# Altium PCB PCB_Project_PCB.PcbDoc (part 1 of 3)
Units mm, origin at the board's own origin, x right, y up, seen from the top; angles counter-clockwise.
Board outline 185 x 95 mm, 2 copper layers (Top Layer, Bottom Layer), stack 1.575 mm thick; 173 components, 93 nets, 424 pads, 126 vias.
Unrouted connection lines stored in the file: 1.
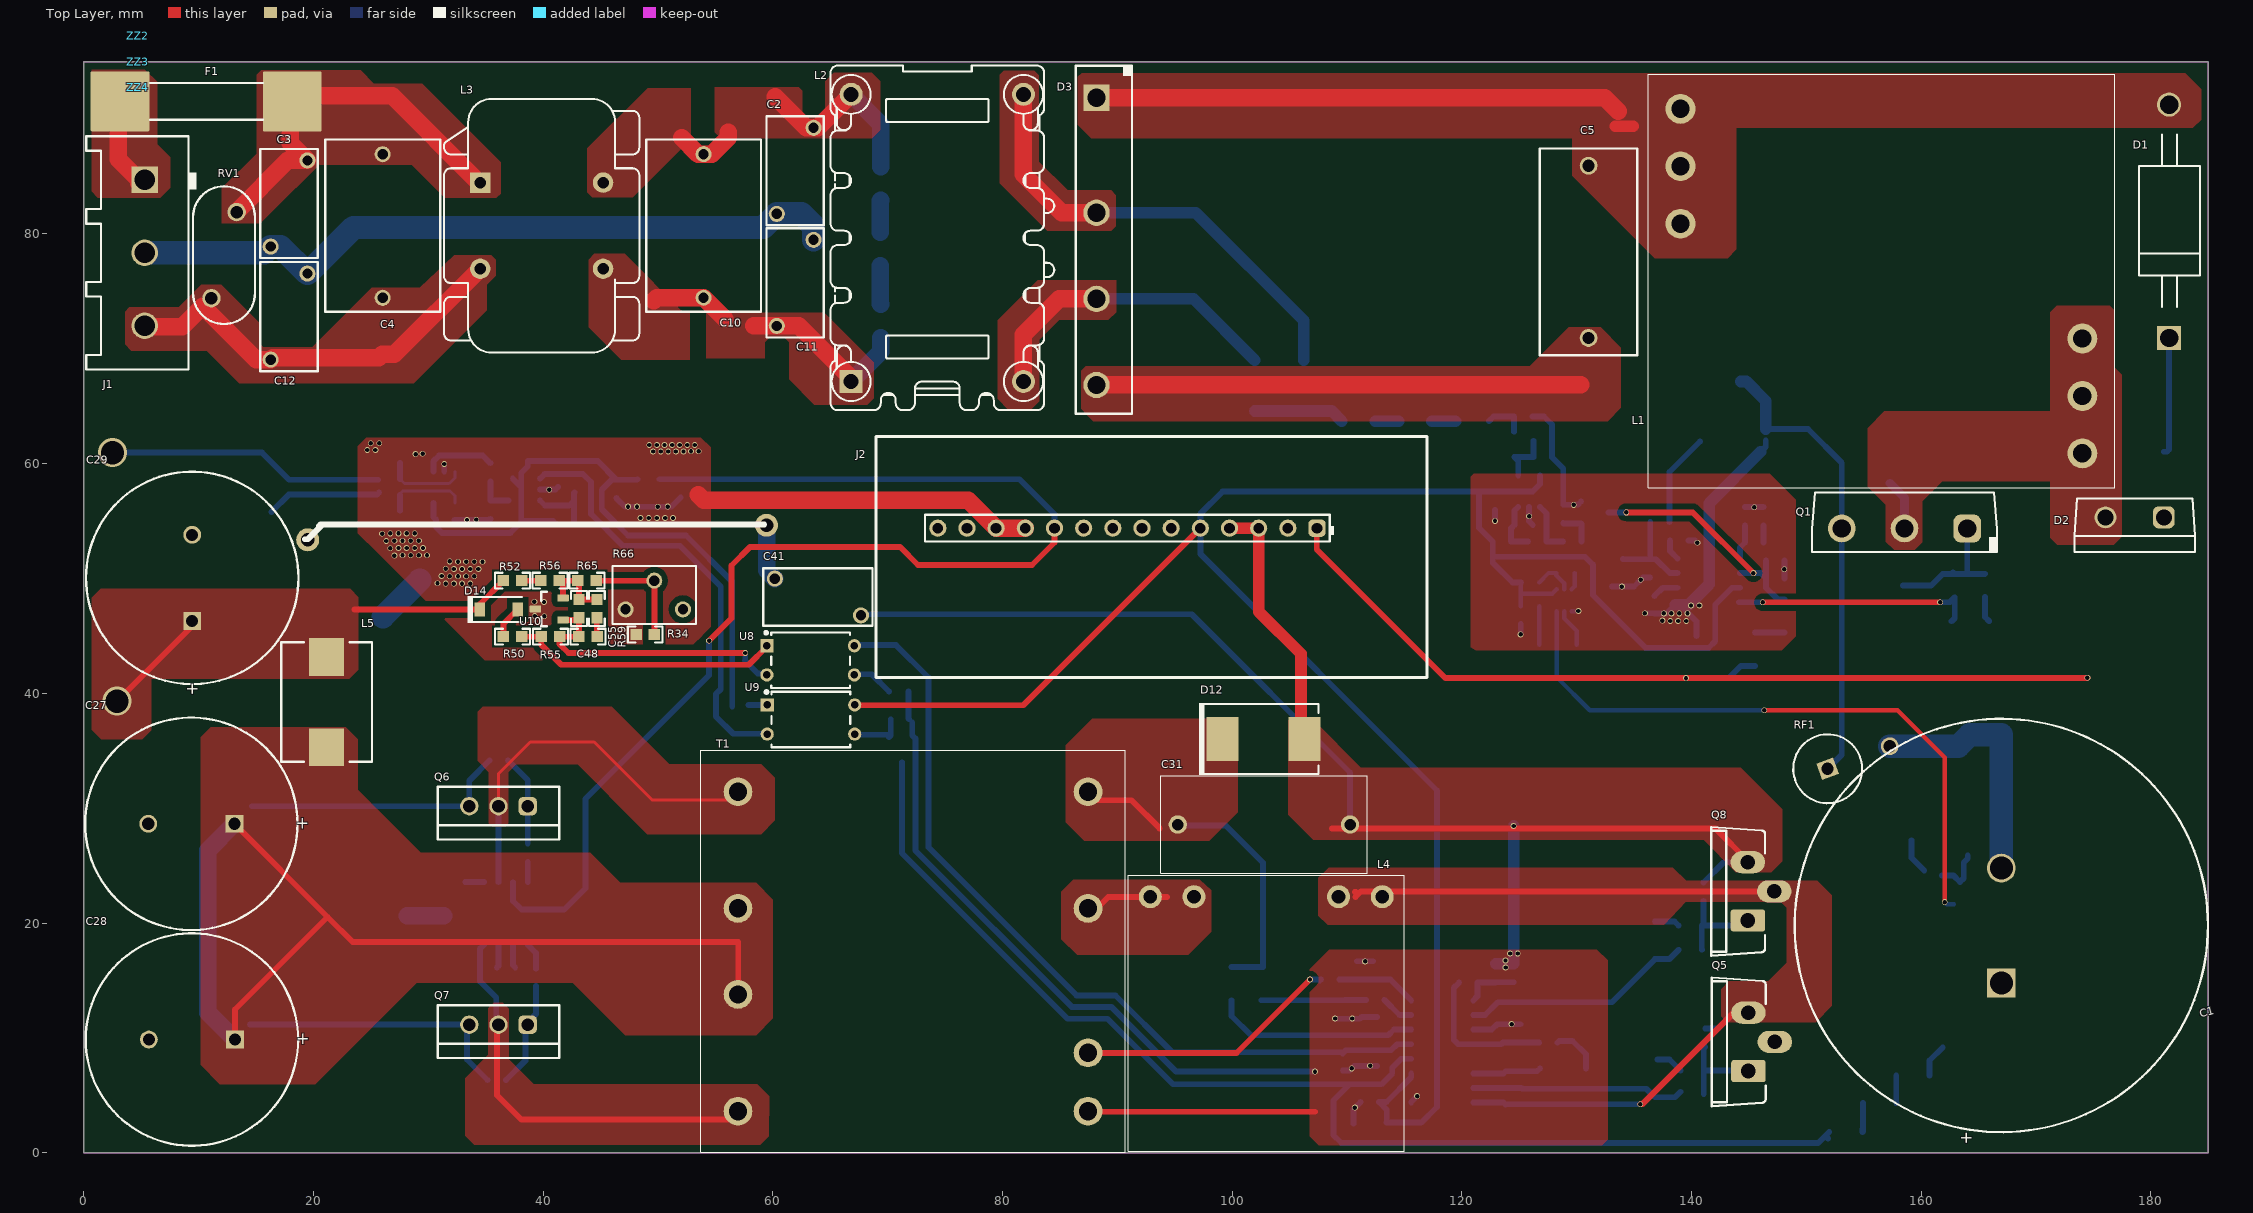
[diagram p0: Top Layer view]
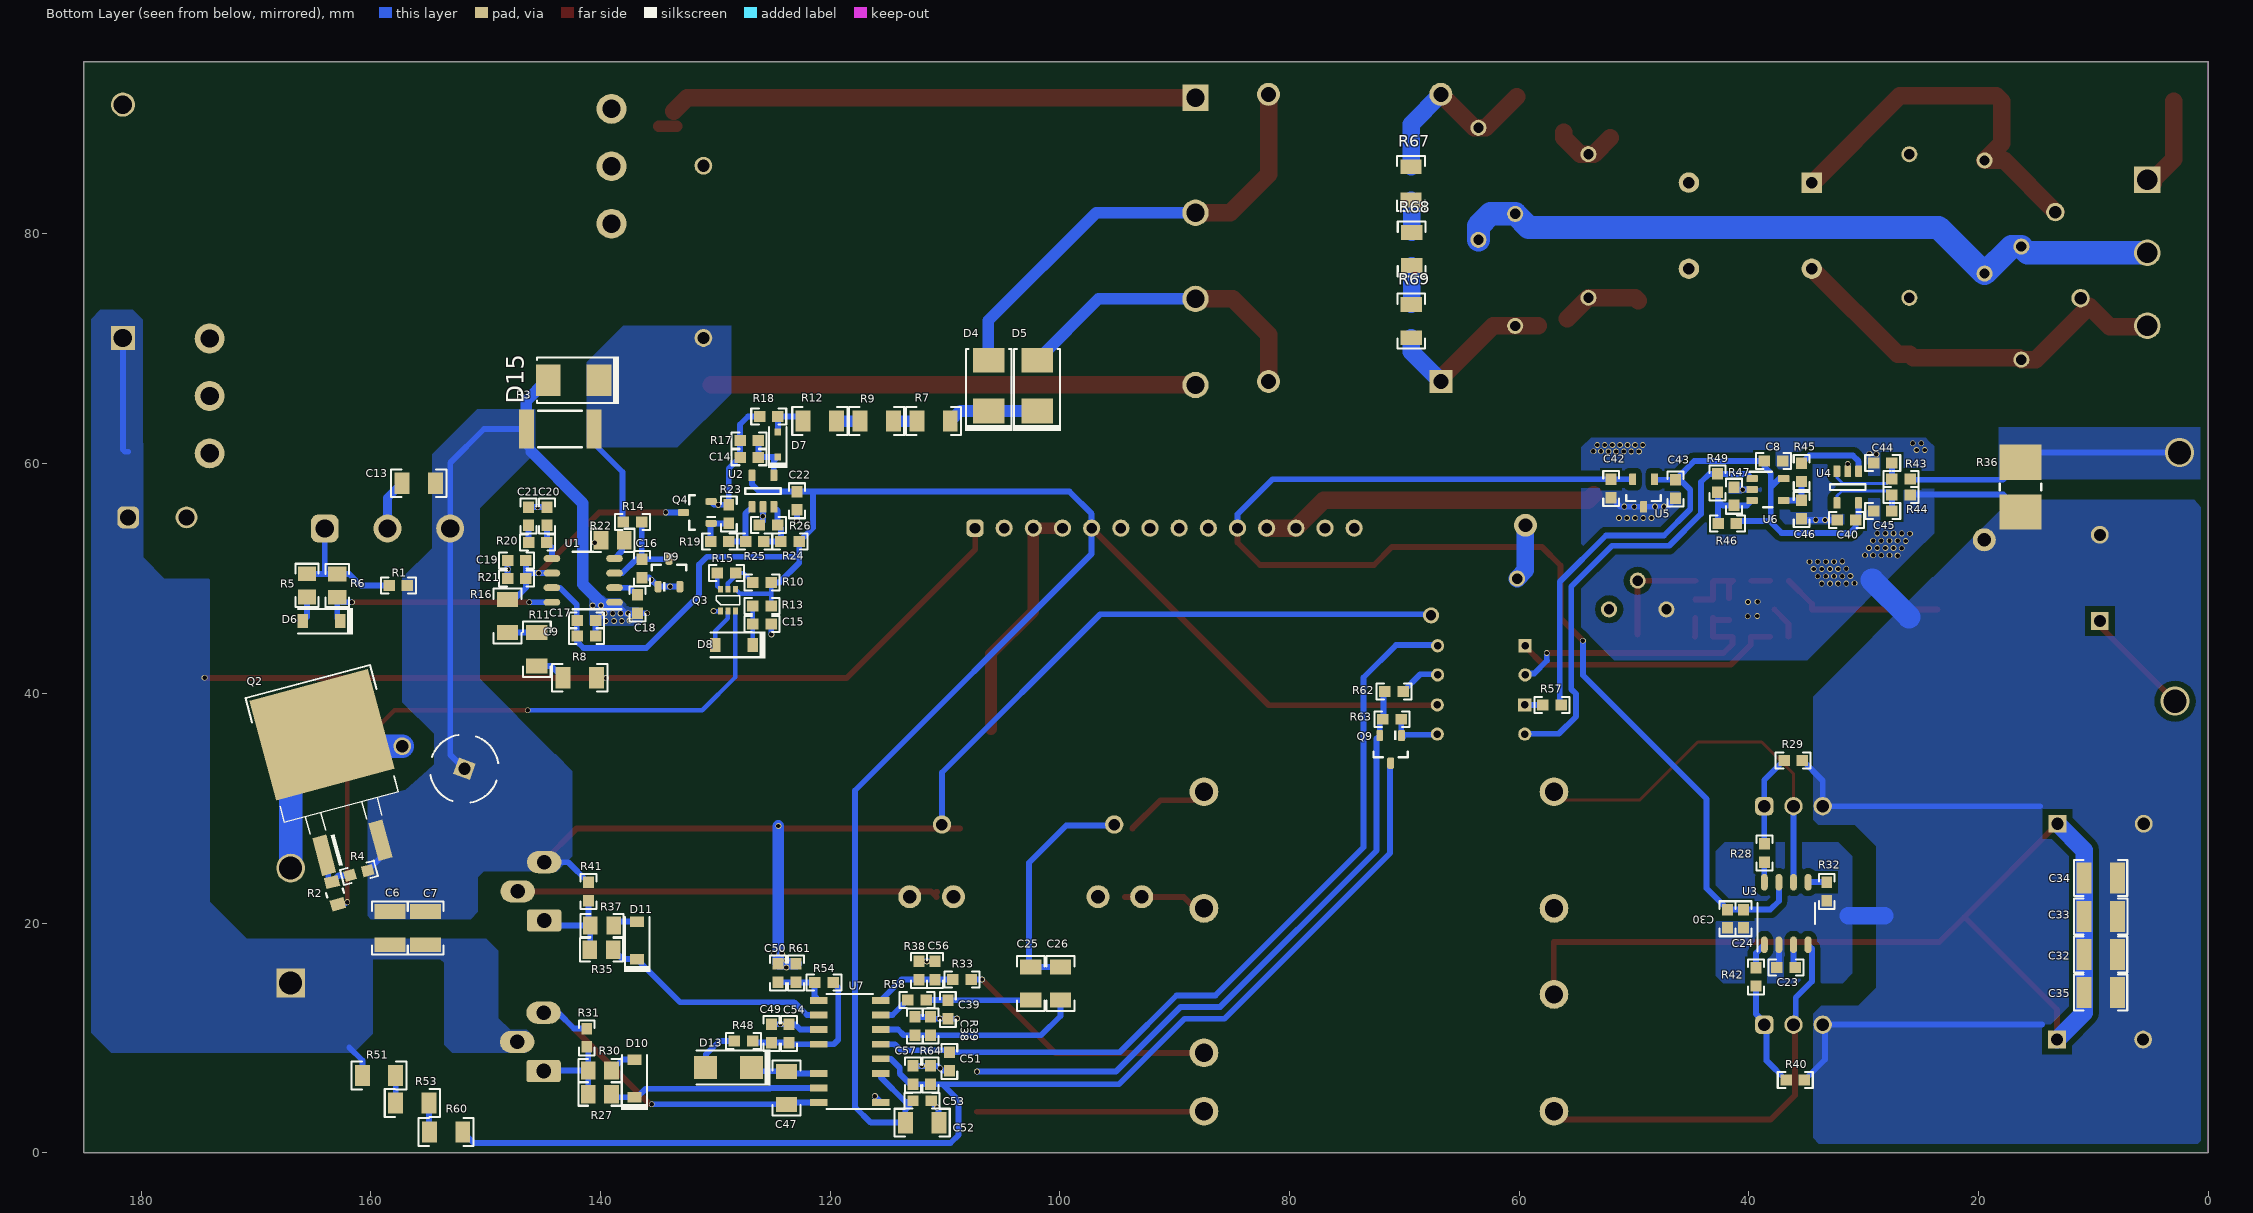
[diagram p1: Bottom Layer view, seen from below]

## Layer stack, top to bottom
Top Solder: solder mask 0.0102, Solder Resist, Dk 3.5
Top Layer: signal copper 0.0356
Dielectric1: core 1.5037, FR-4, Dk 4.8
Bottom Layer: signal copper 0.0356
Bottom Solder: solder mask 0.0102, Solder Resist, Dk 3.5

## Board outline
0,0 185,0 185,95 0,95

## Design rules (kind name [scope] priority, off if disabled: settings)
AcuteAngle [All] p1: minimum=3.00000000000000E+0001 checktracksonly=FALSE
AssemblyTestPointUsage [All] p1: valid=2
BoardOutlineClearance BoardOutlineClearance_MountingHoles [OnCopper and InComponentClass('Mounting Holes')] p1: gap=1.016 ignorepadtopadclearanceinfootprint=FALSE
BoardOutlineClearance BoardOutlineClearance_Poly [OnCopper and IsPoly] p2: gap=0.635 ignorepadtopadclearanceinfootprint=FALSE
BoardOutlineClearance [OnCopper and Not InComponentClass('Logo') and not InComponentClass('FiducialMark') and not InRegion(1000,500,4000,800) and not InPoly] p3: gap=0.508 ignorepadtopadclearanceinfootprint=FALSE
Clearance Clearance_Keepouts [((IsTrack Or IsArc) And Not InPoly) And IsFree and IsKeepOut vs ((IsTrack Or IsArc) And Not InPoly) And IsFree and IsKeepOut] p1: gap=0 ignorepadtopadclearanceinfootprint=FALSE
Clearance Clearance_Poly [InPolygon] p2: gap=0.508 ignorepadtopadclearanceinfootprint=FALSE except(0: Arc-Hole Track-Hole SMDPad-Hole THPad-Hole Via-Hole Fill-Hole Poly-Hole Region-Hole Text-Hole)
Clearance Clearance_FiducialMark [IsKeepOut and InComponentClass('FiducialMark') vs IsPad and InComponentClass('FiducialMark')] p3: gap=0 ignorepadtopadclearanceinfootprint=FALSE
Clearance [All] p4: gap=0.2 ignorepadtopadclearanceinfootprint=FALSE except(0: Arc-Hole Track-Hole SMDPad-Hole THPad-Hole Via-Hole Fill-Hole Poly-Hole Region-Hole Text-Hole)
ComponentClearance ComponentClearance_MountingHoles_FiducialMarks [InComponentClass('Mounting Holes') vs InComponentClass('FiducialMark')] p1: gap=0 collisioncheckmode=3 verticalgap=0 showdistances=FALSE
ComponentClearance ComponentClearance_Shunt [InComponentClass('Header') vs InComponentClass('Shunt')] p2: gap=0 collisioncheckmode=3 verticalgap=0 showdistances=FALSE
ComponentClearance ComponentClearance_Logo [InComponentClass('Logo')] p3: gap=0 collisioncheckmode=3 verticalgap=0 showdistances=FALSE
ComponentClearance ComponentClearance_ScrewToNut [(HasFootprint('NY PMS 440 0025 PH')) vs (HasFootprint('Keystone_1902C'))] p4: gap=0 collisioncheckmode=3 verticalgap=0 showdistances=FALSE
ComponentClearance ComponentClearance_MountingHoles [InComponentClass('Mounting Holes')] p5: gap=6.35 collisioncheckmode=3 verticalgap=2540 showdistances=FALSE
ComponentClearance ComponentClearance_SmallPassives [HasFootprint('0201*') or HasFootprint('0402*') or HasFootprint('0508') or HasFootprint('0603*') or HasFootprint('0612') or HasFootprint('0805*') or HasFootprint('0815*') or HasFootprint('0830*') or HasFootprint('1206*') or HasFootprint('1210*') or HasFootprint('1808*') or HasFootprint('1812*') or HasFootprint('1825*') or HasFootprint('2010*') or HasFootprint('2220*') or HasFootprint('2225*') or HasFootprint('2512*') or HasFootprint('2728*') or HasFootprint('3518*') vs HasFootprint('0201*') or HasFootprint('0402*') or HasFootprint('0508') or HasFootprint('0603*') or HasFootprint('0612') or HasFootprint('0805*') or HasFootprint('0815*') or HasFootprint('0830*') or HasFootprint('1206*') or HasFootprint('1210*') or HasFootprint('1808*') or HasFootprint('1812*') or HasFootprint('1825*') or HasFootprint('2010*') or HasFootprint('2220*') or HasFootprint('2225*') or HasFootprint('2512*') or HasFootprint('2728*') or HasFootprint('3518*')] p6: gap=0.38 collisioncheckmode=3 verticalgap=0.254 showdistances=FALSE
ComponentClearance ComponentClearance_THtoSMT [IsThruComponent vs IsSMTComponent] p7: gap=0 collisioncheckmode=3 verticalgap=0 showdistances=FALSE
ComponentClearance ComponentClearance_THtoTH [IsThruComponent vs IsThruComponent] p8: gap=0 collisioncheckmode=3 verticalgap=0 showdistances=FALSE
ComponentClearance [All] p9: gap=0 collisioncheckmode=3 verticalgap=0 showdistances=FALSE
DiffPairsRouting [All] p1: maxlimit=2.54 minlimit=0.254 mostfreqgap=0.254 toplayer_minwidth=0.381 toplayer_maxwidth=0.381 toplayer_prefwidth=0.381 bottomlayer_minwidth=0.381 bottomlayer_maxwidth=0.381 bottomlayer_prefwidth=0.381 maxuncoupledlength=25.4
FabricationTestPointUsage TestPointUsage [All] p1: valid=2 allowmultiple=FALSE
FabricationTestpoint Testpoint [All] p1: side=3 testpointundercomponent=TRUE minsize=1.016 maxsize=2.54 preferedsize=1.524 minholesize=0 maxholesize=1.016 preferedholesize=0.813 testpointgrid=0.025 allowsidetop=TRUE allowsidebottom=TRUE usegrid=TRUE gridtolerance=0
FanoutControl Fanout_LCC [IsLCC] p1: bgadir=Out bgaviamode=Centered fanoutstyle=Auto fanoutdirection=Alternating viagrid=0.025 // Fanout_LCC (Default Rule)
FanoutControl Fanout_BGA [IsBGA] p2: bgadir=Out bgaviamode=Centered fanoutstyle=Auto fanoutdirection=Alternating viagrid=0.025 // Fanout_BGA (Default Rule)
FanoutControl Fanout_Default [All] p4: bgadir=Out bgaviamode=Centered fanoutstyle=Auto fanoutdirection=Alternating viagrid=0.025 // Fanout_Default (Default Rule)
FanoutControl Fanout_Small [(CompPinCount < 5)] p5: bgadir=Out bgaviamode=Centered fanoutstyle=Auto fanoutdirection=OutThenIn viagrid=0.025 // Fanout_Small (Default Rule)
Height [All] p1: minheight=0 maxheight=50 prefheight=12.7
HoleSize [All] p1: absolutevalues=TRUE maxlimit=6.375 minlimit=0.1 maxpercent=80.000 minpercent=20.000
HoleToHoleClearance [All] p1: gap=0 allowstackedmicrovias=TRUE
MinimumAnnularRing MinimumAnnularRing_ThermalPadVias [IsVia and InAnyComponent] p1: minimumring=0
MinimumAnnularRing [All] p2: minimumring=0
MinimumSolderMaskSliver MinimumSolderMaskSliver_Logo [InComponentClass('Logo') vs InComponentClass('Logo')] p1: minsoldermaskwidth=0
MinimumSolderMaskSliver [All] p2: minsoldermaskwidth=0
PlaneConnect [All] p1: planeconnectstyle=Relief reliefexpansion=0.254 reliefentries=4 reliefconductorwidth=0.254 reliefairgap=0.254
PolygonConnect [All] p1: connectstyle=Direct reliefconductorwidth=0.254 reliefentries=4 polygonreliefangle="90 Angle" airgapwidth=0.254
RoutingVias ThermalPadVias [IsVia and InAnyComponent] p1: holewidth=0.381 width=0.508 viastyle="Through Hole" minholewidth=0.127 minwidth=0.254 maxholewidth=7.62 maxwidth=10.16
RoutingVias [All] p2: holewidth=0.381 width=0.508 viastyle="Through Hole" minholewidth=0.127 minwidth=0.254 maxholewidth=7.62 maxwidth=10.16
SilkToBoardRegionClearance [Not ((IsComment or IsDesignator) And (Hide <> 'False')) and not InRegion(1000,500,4000,800)] p1:
SilkToSilkClearance SilkToSilkClearance_Pb-FreeLogo [(HasFootprint('Pb-Free_Overlay_Medium') OR HasFootprint('Pb-Free_Overlay_Small')) vs (HasFootprint('Pb-Free_Overlay_Medium') OR HasFootprint('Pb-Free_Overlay_Small'))] p1: silktosilkclearance=0
SilkToSilkClearance [All] p2: silktosilkclearance=0
SilkToSolderMaskClearance SilkToComponentPadClearance [(IsPad or IsFill or IsRegion) and InAnycomponent] p1: minsilkscreentomaskgap=0 clearancetoexposedcopper=TRUE
SilkToSolderMaskClearance "Silk to Solder Mask Opening" [All] p2: minsilkscreentomaskgap=0 clearancetoexposedcopper=TRUE
SolderMaskExpansion [All] p1: expansion=0.05
Width [All] p1: maxlimit=2.54 minlimit=0.152 preferedwidth=0.254 checkconnectedcopper=TRUE
13 further rules are at their usual default settings.

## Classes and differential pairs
component class AssemblyNote: ZZ1 ZZ2 ZZ3 ZZ4
component class PCB_Project_EVM_Hardware: ZZ1 ZZ2 ZZ3 ZZ4
component class Header: J2
component class LLC: C8 C23 C24 C25 C26 C27 C28 C29 C30 C31 C32 C33 C34 C35 C38 C39 C40 C41 C42 C43 C44 C45 C46 C47 C48 C49 C50 C51 C52 C53 C54 C55 C56 C57 D10 D11 D12 D13 D14 L4 L5 Q5 Q6 Q7 Q8 Q9 R27 R28 R29 R30 R31 R32 R33 R34 R35 R36 R37 R38 R39 R40 R41 R42 R43 R44 R45 R46 R47 R48 R49 R50 R51 R52 R53 R54 R55 R56 R57 R58 R59 R60 R61 R62 R63 R64 R65 R66 T1 U3 U4 U5 U6 U7 U8 U9 U10
component class PFC: C1 C2 C3 C4 C5 C6 C7 C9 C10 C11 C12 C13 C14 C15 C16 C17 C18 C19 C20 C21 C22 D1 D2 D3 D4 D5 D6 D7 D8 D9 D15 F1 H1 J1 J2 L1 L2 L3 Q1 Q2 Q3 Q4 R1 R2 R3 R4 R5 R6 R7 R8 R9 R10 R11 R12 R13 R14 R15 R16 R17 R18 R19 R20 R21 R22 R23 R24 R25 R26 R67 R68 R69 RF1 RV1 U1 U2
net class HV: 390V NetC5_1 NetC13_1 NetC25_1 NetL4_2

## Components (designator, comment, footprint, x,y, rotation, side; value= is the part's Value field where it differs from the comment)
C1 "330 uF, 450 V" WCAP-AIG8_3500x3700 166.98,19.787 r90 top value=330uF
C2 "AY2222M35Y5US63L7" AY2_950x500_Straight 61.951,85.496 r270 top value=2200pF
C3 "AY2222M35Y5US63L7" AY2_950x500_Straight 17.882,82.652 r90 top value=2200pF
C4 "890324024005" WCAP-FTX2_1500x1000x1600 26.035,80.694 r270 top value=0.47uF
C5 "B32522N6474J" B32522_1800x850x1450 131.039,78.442 r270 top value=0.47uF
C6 "C3225X7T2J104M160AC" 1210_180 158.344,19.558 r90 bottom value=0.1uF
C7 "C3225X7T2J104M160AC" 1210_180 155.245,19.558 r90 bottom value=0.1uF
C8 "C1608X5R1E105K080AC" 0603 37.871,60.223 r180 bottom value=1uF
C9 "GRM188R61E104KA01D" 0603 141.224,44.983 r180 bottom value=0.1uF
C10 "890324024005" WCAP-FTX2_1500x1000x1600 53.975,80.696 r270 top value=0.47uF
C11 "AY2222M35Y5US63L7" AY2_950x500_Straight 61.951,75.743 r270 top value=2200pF
C12 "AY2222M35Y5US63L7" AY2_950x500_Straight 17.882,72.806 r270 top value=2200pF
C13 "GRM31A5C2J101JW01D" 1206 155.829,58.293 r180 bottom value=100pF
C14 "GRM188R6YA225KA12D" 0603 127.051,60.554 r0 bottom value=2.2uF
C15 "GCM188R71E474KA64D" 0603 125.933,46.05 r180 bottom value=0.47uF
C16 "GRM188R71E152KA01D" 0603 136.398,50.876 r270 bottom value=1500pF
C17 "GRM188R61E475KE11D" 0603 141.224,46.355 r180 bottom value=4.7uF
C18 "GRM188R71C472KA01D" 0603 136.779,47.777 r270 bottom value=4700pF
C19 "GRM1885C1E821JA01D" 0603 147.295,51.562 r0 bottom value=820pF
C20 "GRM188R71C474KA88D" 0603 144.653,55.422 r90 bottom value=0.47uF
C21 "GRM188Z71C225KE43" 0603 146.279,55.422 r90 bottom value=2.2uF
C22 "C1608X7R1H104K080AA" 0603 122.885,56.769 r270 bottom value=0.1uF
C23 "EMK107BB7225KA-T" 0603 36.779,16.129 r0 bottom value=2.2uF
C24 "GRM188R61E475KE11D" 0603 40.488,20.371 r270 bottom value=4.7uF
C25 "GRM31A7U3A680JW31D" 1206 102.54,14.732 r270 bottom value=68pF
C26 "GRM31A5C2J331JW01D" 1206 99.949,14.732 r270 bottom value=330pF
C27 "EGPA800ELL681MM30S" GPA_1800x3000 9.373,28.642 r180 top value=680uF
C28 "EGPA800ELL681MM30S" GPA_1800x3000 9.423,9.855 r180 top value=680uF
C29 "EGPA800ELL681MM30S" GPA_1800x3000 9.449,50.054 r90 top value=680uF
C30 "GRM188R61E104KA01D" 0603 41.859,20.371 r270 bottom value=0.1uF
C31 "R73PN2820SE00J" "resonant cap" 102.768,28.575 r0 top value=0.082uF
C32 "GRM32ER71J106KA12L" 1210_270 9.373,17.247 r180 bottom value=10uF
C33 "GRM32ER71J106KA12L" 1210_270 9.37,20.574 r180 bottom value=10uF
C34 "GRM32ER71J106KA12L" 1210_270 9.373,23.901 r180 bottom value=10uF
C35 "GRM32ER71J106KA12L" 1210_270 9.373,13.945 r180 bottom value=10uF
C38 "06033C101KAT2A" 0603 112.628,11.024 r90 bottom value=100pF
C39 "GRM188R71E822KA01D" 0603 109.758,12.471 r270 bottom value=8200pF
C40 "C1608X5R1E105K080AC" 0603 31.496,55.105 r0 bottom value=1uF
C41 "AY2222M35Y5US63L7" AY2_950x500_Straight 63.932,48.387 r180 top value=2200pF
C42 "GRM188R71H104KA93D" 0603 51.994,57.848 r270 bottom value=0.1uF
C43 "GCM188R71C105MA64D" 0603 46.38,57.798 r270 bottom value=1uF
C44 "GRM188R71H103KA01D" 0603 28.346,60.058 r0 bottom value=0.01uF
C45 "GRM188R71H103KA01D" 0603 28.346,55.893 r0 bottom value=0.01uF
C46 "GRM188R71E103KA01D" 0603 35.408,55.994 r270 bottom value=0.01uF
C47 "12063C105KAT2A" 1206 123.804,5.639 r270 bottom value=1uF
C48 "GRM188R71E124KA01D" 0603 43.917,44.933 r180 top value=0.12uF
C49 "06033C101KAT2A" 0603 125.099,10.389 r90 bottom value=100pF
C50 "GRM188R71C334KA01D" 0603 124.536,15.646 r90 bottom value=0.33uF
C51 "06031C102JAT2A" 0603 109.626,7.95 r270 bottom value=1000pF
C52 "C3216JB1E476M160AC" 1206 111.989,2.616 r180 bottom value=47uF
C53 "C1608X7R1H104K080AA" 0603 111.989,4.521 r180 bottom value=0.1uF
C54 "GRM188R61E475KE11D" 0603 123.575,10.389 r270 bottom value=4.7uF
C55 "GRM1885C1H100JA01D" 0603 43.129,47.371 r270 top value=10pF
C56 "06033C101KAT2A" 0603 110.875,15.875 r90 bottom value=100pF
C57 "GRM188R71C103KA01D" 0603 112.776,6.756 r90 bottom value=0.01uF
D1 "1N5406" DO-201AD 181.585,81.102 r90 top value=600V
D2 "MUR860G" TO-220AC 178.587,55.321 r180 top value=600V
D3 "LVB2560" GBJ 88.189,79.35 r270 top value=1000V
D4 "RS1MB-13-F" SMB 106.197,66.802 r90 bottom value=1000V
D5 "RS1MB-13-F" SMB 101.981,66.802 r90 bottom value=1000V
D6 "1N4148W-7-F" SOD-123 164.287,46.279 r0 bottom value=70V
D7 "BAT54HT1G" sod-323 124.562,61.671 r90 bottom value=30V
D8 "MMSZ4690T1G" SOD-123 128.372,44.221 r0 bottom value=5.6V
D9 "BAV23C,215" SOT-23 134.036,50.495 r90 bottom value=250V
D10 "1N4148W-7-F" SOD-123 137.033,6.477 r90 bottom value=70V
D11 "1N4148W-7-F" SOD-123 136.804,18.491 r90 bottom value=70V
D12 "STTH3R06S" SMC 102.718,36.017 r0 top value=600V
D13 "US1J-13-F" SMA 128.854,7.417 r0 bottom value=600V
D14 "MMSZ5256B-7-F" SOD-123 36.144,47.295 r0 top value=30V
D15 "RS1MB-13-F" SMB 142.342,67.261 r0 bottom value=1000V
F1 "0215010.MXP" FUSE 18.161,91.542 r180 top
J1 "350429-1" TE_350429-1 5.309,78.359 r270 top
J2 "4-644694-4" "AUX POWER" 107.391,54.381 r180 top
L1 "Inductor" PFC_L 156.54,75.895 r0 top
L2 "8113-RC" WE-CMB_XL 74.327,79.658 r90 top value="5 mH"
L3 "4.5mH" WE-CMB_M 39.878,80.721 r0 top
L4 "Inductor" LLC_LR 102.972,12.141 r90 top value=31uH
L5 "PA2607.301NLT" PA2607NL_7R5mm 21.158,39.243 r90 top value=300nH
Q1 "IPW60R099CPFKSA1" TO-247 158.547,54.356 r180 top value=600V
Q2 "TK20G60W,RVQ" DDPAK 163.22,32.588 r75 bottom value=600V
Q3 "BC 846PN H6327" SOT-363 128.905,48.113 r90 bottom value="65 V"
Q4 "2N7002" SOT-23 131.572,55.753 r0 bottom value=60V
Q5 "SPP20N65C3XKSA1" TO-220 144.958,9.652 r270 top value=650V
Q6 "IPP075N15N3GXKSA1" TO-220-3 36.119,30.175 r180 top value=150V
Q7 "IPP075N15N3GXKSA1" TO-220-3 36.119,11.151 r180 top value=150V
Q8 "SPP20N65C3XKSA1" TO-220 144.907,22.758 r270 top value=650V
Q9 "2N7002" SOT-23 71.196,35.128 r270 bottom value=60V
R1 "CRCW060310K0JNEA" 0603 157.607,49.378 r0 bottom value=10k
R2 "CRCW080518R2FKEA" 0805_HV1 163.119,22.606 r255 bottom value=18.2
R3 "CSRN2512FK20L0" 2512 143.51,63.017 r0 bottom value=0.02
R4 "ERJ-3EKF4992V" 0603 161.036,24.359 r165 bottom value=49.9k
R5 "CRCW08053R30JNEA" 0805_HV 165.557,49.403 r90 bottom value=3.3
R6 "CRCW080510R0JNEA" 0805_HV 162.916,49.378 r90 bottom value=10
R7 "CRCW12063M00JNEA" 1206 110.998,63.703 r180 bottom value=3.0Meg
R8 "CRCW1206330KJNEA" 1206 141.808,41.351 r180 bottom value=330k
R9 "CRCW12063M00JNEA" 1206 115.951,63.703 r180 bottom value=3.0Meg
R10 "RC0603JR-0710KL" 0603 125.946,49.662 r180 bottom value=10k
R11 "CRCW1206340KFKEA" 1206 145.542,43.84 r270 bottom value=340k
R12 "CRCW12063M00JNEA" 1206 120.904,63.703 r180 bottom value=3.0Meg
R13 "CRCW06031K00JNEA" 0603 125.933,47.6 r180 bottom value=1.0k
R14 "CRCW0603220RJNEA" 0603 137.211,54.915 r0 bottom value=220
R15 "CRCW0603100KJNEA" 0603 129.02,50.475 r180 bottom value=100k
R16 "CRCW1206330KJNEA" 1206 148.107,46.736 r270 bottom value=330k
R17 "CRCW06032M00JNEA" 0603 127.051,62.001 r180 bottom value=2.0Meg
R18 "CRCW0603100KJNEA" 0603 125.349,64.11 r180 bottom value=100k
R19 "CRCW060312K0JNEA" 0603 129.616,53.213 r180 bottom value=12k
R20 "CRCW060322K0JNEA" 0603 145.466,53.137 r180 bottom value=22k
R21 "CRCW060313K0FKEA" 0603 147.295,50.013 r180 bottom value=13.0k
R22 "CRCW080533K0JNEA" 0805_HV 138.938,53.315 r180 bottom value=33k
R23 "RC0603JR-0724KL" 0603 128.829,55.626 r270 bottom value=24k
R24 "CRCW0603127KFKEA" 0603 123.495,53.213 r180 bottom value=127k
R25 "CRCW06031M18FKEA" 0603 126.568,53.208 r0 bottom value=1.18Meg
R26 "CRCW06039K10JNEA" 0603 125.374,54.661 r180 bottom value=9.1k
R27 "RC0805FR-075R6L" 0805_HV 140.056,5.105 r0 bottom value=5.60
R28 "CRCW06032R00JNEA" 0603 38.659,26.111 r270 bottom value=2.0
R29 "CRCW0603100KJNEA" 0603 36.144,34.163 r180 bottom value=100k
R30 "RC0805FR-071RL" 0805_HV 140.056,7.163 r0 bottom value=1.00
R31 "CRCW060310K0JNEA" 0603 141.199,10.008 r270 bottom value=10k
R32 "CRCW060330R0JNEA" 0603 33.223,22.758 r90 bottom value=30
R33 "CRCW060333K0JNEA" 0603 108.534,15.088 r180 bottom value=33k
R34 "CRCW060351K0JNEA" 0603 48.895,45.136 r0 top value=51k
R35 "RC0805FR-075R6L" 0805_HV 139.903,17.678 r0 bottom value=5.60
R36 "WSL2512L5000FEA18" WSL2512_-0005 16.358,57.963 r90 bottom value=0.0005
R37 "RC0805FR-071RL" 0805_HV 139.878,19.787 r0 bottom value=1.00
R38 "CRCW06038K20JNEA" 0603 112.272,15.875 r270 bottom value=8.2k
R39 "CRCW060368R0JNEA" 0603 111.256,11.024 r270 bottom value=68
R40 "CRCW0603100KJNEA" 0603 35.966,6.325 r180 bottom value=100k
R41 "CRCW060310K0JNEA" 0603 141.046,22.733 r270 bottom value=10k
R42 "CRCW06032R00JNEA" 0603 39.395,15.316 r270 bottom value=2.0
R43 "CRCW060310R0FKEAHP" 0603 26.746,58.661 r180 bottom value=10.0
R44 "CRCW060310R0FKEAHP" 0603 26.746,57.264 r180 bottom value=10.0
R45 "RC0603JR-071KL" 0603 35.408,59.245 r270 bottom value=1.0k
R46 "CRCW060310K0JNEA" 0603 41.885,54.788 r0 bottom value=10k
R47 "CRCW060324K3FKEA" 0603 41.3,57.163 r270 bottom value=24.3k
R48 "CRCW06032R00JNEA" 0603 127.559,9.728 r0 bottom value=2.0
R49 "CRCW0603110KJNEA" 0603 42.748,58.306 r270 bottom value=110k
R50 "CRCW060310K0JNEA" 0603 37.351,44.933 r180 top value=10k
R51 "CRCW12065M10JNEA" 1206 159.283,6.731 r0 bottom value=5.1Meg
R52 "CRCW060375K0JNEA" 0603 37.338,49.809 r180 top value=75k
R53 "CRCW12065M10JNEA" 1206 156.388,4.318 r0 bottom value=5.1Meg
R54 "CRCW0603470KJNEA" 0603 120.553,14.808 r180 bottom value=470k
R55 "CRCW06036K04FKEA" 0603 40.64,44.933 r180 top value=6.04k
R56 "CRCW0603130KJNEA" 0603 40.589,49.809 r180 top value=130k
R57 "RC1608J103CS" 0603 57.15,38.989 r180 bottom value=10k
R58 "RMCF0603ZT0R00" 0603 112.45,13.31 r0 bottom value=0
R59 "CRCW060310K0JNEA" 0603 44.679,47.371 r270 top value=10k
R60 "CRCW12065M60JNEA" 1206 153.444,1.803 r0 bottom value=5.6Meg
R61 "CRCW0603330KJNEA" 0603 122.966,15.646 r270 bottom value=330k
R62 "CRCW06030000Z0EA" 0603 70.917,40.157 r180 bottom value=0
R63 "RC1608J103CS" 0603 71.069,37.744 r0 bottom value=10k
R64 "CRCW0603127KFKEA" 0603 111.256,6.756 r270 bottom value=127k
R65 "CRCW06039K10JNEA" 0603 43.84,49.809 r180 top value=9.1k
R66 "PV37W502C01B00" Bourns_PV37W 49.682,48.559 r90 top value="5k Ohm"
R67 "RC1206FR-07330KL" 1206 69.418,84.404 r90 bottom value=330k
R68 "RC1206FR-07330KL" 1206 69.367,78.689 r90 bottom value=330k
R69 "RC1206FR-07330KL" 1206 69.407,72.415 r90 bottom value=330k
RF1 "EMC2-47RKI" "inrush res" 151.892,33.477 r20 top value=47
RV1 "S10K275E2" VAR_S10K275E2 12.217,78.156 r90 top value=275V
T1 "750343737" LLC_T 72.212,17.526 r180 top
U1 "UCC28180DR" D0008A_N 141.503,49.834 r0 bottom
U2 "TLV9101" DBV0005A_N 125.857,57.607 r90 bottom
U3 "PUCC24624D" D0008A_N 36.754,20.828 r90 bottom
U4 "INA180A4IDBV" DBV0005A_N 31.394,57.95 r270 bottom
U5 "TLV76033DBZR" DBZ0003A_N 49.174,57.442 r270 bottom
U6 "TLV9001IDBVR" DBV0005A_N 38.354,57.747 r180 bottom
U7 "UCC25630-3DDBR" DDB0014A 118.292,8.814 r0 bottom
U8 "VO618A" DIP-4 63.297,42.875 r0 top
U9 "VO618A" DIP-4 63.322,37.719 r0 top
U10 "ATL431BQDBZR" DBZ0003A_N 40.538,47.346 r180 top
ZZ1 "This Assembly Note is for PCB labels only" AssemblyNoteLabel 4.699,100.025 r0 top
ZZ2 "These assemblies are ESD sensitive, ESD precautions shall be observed." AssemblyNote 4.699,97.259 r0 top
ZZ3 "These assemblies must be clean and free from flux and all contaminants. Use of no clean flux is not acceptable." AssemblyNote 4.699,95.01 r0 top
ZZ4 "These assemblies must comply with workmanship standards IPC-A-610 Class 2, unless otherwise specified." AssemblyNote 4.699,92.761 r0 top

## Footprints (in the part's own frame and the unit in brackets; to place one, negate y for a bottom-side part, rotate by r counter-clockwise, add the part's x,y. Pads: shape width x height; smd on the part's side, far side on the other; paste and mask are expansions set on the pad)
0603 [mm] "0603 from SM-752 data"
  rect 1x0.95 smd: 1(-0.8,0) 2(0.8,0)
  silkscreen extent -1.52,-0.69 1.52,0.69, body extent -0.87,-0.47 0.87,0.47, height 1
0805_HV [mil] "0805 with 30mil clearance between pads"
  rect 50x63 smd: 1(-40,0) 2(40,0)
  silkscreen extent -74,-40 74,40, body extent -43,-29 43,29, height 57
0805_HV1 [mm] "Custom footprint based on analyzing multiple manufacturer recommendations"
  rrect10% 1x1.25 smd: 1(-1,0) 2(1,0)
  silkscreen extent -0.2,-0.75 0.2,0.75, body extent -1.1,-0.72 1.1,0.73, height 1.45
1206 [mm] "1206 from SM-752 data"
  rect 1.3x1.85 smd: 1(-1.45,0) 2(1.45,0)
  silkscreen extent -2.4,-1.21 2.4,1.21, body extent -1.7,-0.9 1.7,0.9, height 1.35
1210_180 [mm] "1210"
  rect 1.3x2.7 smd: 1(-1.45,0) 2(1.45,0)
  silkscreen extent -2.32,-1.57 2.32,1.57, body extent -1.7,-1.35 1.7,1.35, height 1.8
1210_270 [mm] "1210"
  rect 1.3x2.7 smd: 1(-1.45,0) 2(1.45,0)
  silkscreen extent -2.32,-1.57 2.32,1.57, body extent -1.7,-1.35 1.7,1.35, height 2.7
2512 [mm] "Chip Resistor, Body 6.3x3.2mm, IPC Medium Density"
  rect 1.3x3.4 smd: 1(-2.95,0) 2(2.95,0)
  silkscreen extent -1.9,-1.6 1.9,1.6, body extent -3.22,-1.67 3.22,1.67, height 0.71
AssemblyNote [mm] "Assembly Note"
AssemblyNoteLabel [mm] "Assembly Note for PCB Labels"
"AUX POWER" [mm]
  rrect50% 1.5x1.5 hole 0.94: 1(0,0)
  round 1.5 hole 0.94: 2(2.54,0) 3(5.08,0) 4(7.62,0) 5(10.16,0) 6(12.7,0) 7(15.24,0) 8(17.78,0) 9(20.32,0) 10(22.86,0) 11(25.4,0) 12(27.94,0) 13(30.48,0) 14(33.02,0)
  silkscreen extent -9.58,-8 38.42,13
AY2_950x500_Straight [mm] "TH, 2-Leads, 9.5x5mm, Pin Spacing 7.5mm"
  round 1.4 hole 0.9: 1(-3.75,1.6) 2(3.75,-1.6)
  silkscreen extent -4.75,-2.5 4.75,2.5, body extent -4.74,-2.5 4.75,2.5, height 12.5
B32522_1800x850x1450 [mm] "TH, 2-Leads, Body 18x8.5mm, PinSpacing 15mm"
  round 1.55 hole 1.05: 1(-7.5,0) 2(7.5,0)
  silkscreen extent -9,-4.25 9,4.25, body extent -9,-4.25 9,4.25, height 14.5
Bourns_PV37W [mm] "TH, 3-Leads, Body 6.71x4.5mm"
  round 1.4 hole 0.9: 1(-1.25,2.5) 2(1.25,0) 3(-1.25,-2.5)
  silkscreen extent -2.52,-3.63 2.52,3.63, body extent -2.44,-3.54 2.44,3.54, height 8.39
D0008A_N [mm] "SOIC, 8-Leads, Body 4.9x3.9mm, Pitch 1.27mm, IPC Medium Density"
  oval 1.45x0.6 smd: 1(-2.725,1.905) 2(-2.725,0.635) 3(-2.725,-0.635) 4(-2.725,-1.905) 5(2.725,-1.905) 6(2.725,-0.635) 7(2.725,0.635) 8(2.725,1.905)
  silkscreen extent -3.3,-2.5 0.9,2.5, body extent -3,-2.45 3,2.45, height 1.63
DBV0005A_N [mm] "SOT23, 5-Leads, Body 2.9x1.6mm, Pitch 0.95mm, Lead Span 2.8mm, IPC Medium Density"
  rrect17% 1x0.6 smd: 1(-1.375,0.95) 2(-1.375,0) 3(-1.375,-0.95) 4(1.375,-0.95) 5(1.375,0.95)
  silkscreen extent -0.25,-1.55 0.25,1.55, body extent -1.42,-1.46 1.42,1.46, height 1.09
DBZ0003A_N [mm] "SOT23, 3-Leads, Body 2.9x1.3mm, Pitch 0.95mm, Lead Span 2.4mm, IPC Medium Density"
  rrect17% 1x0.6 smd: 1(-1.2,0.95) 2(-1.2,-0.95) 3(1.2,0)
  silkscreen extent 0.2,-1.5 0.7,1.5, body extent -1.26,-1.46 1.26,1.46, height 0.98
DDB0014A [mm] "SMD, 14-Leads, Body 3.9x9.9mm, Pitch 1.27mm"
  rrect17% 1.55x0.6 smd: 1(-2.7,4.445) 3(-2.7,1.905) 4(-2.7,0.635) 5(-2.7,-0.635) 6(-2.7,-1.905) 7(-2.7,-3.175) 8(-2.7,-4.445) 9(2.7,-4.445) 10(2.7,-3.175) 11(2.7,-1.905) 12(2.7,-0.635) 14(2.7,1.905) 15(2.7,3.175) 16(2.7,4.445)
  silkscreen extent -3.5,-5 2,5, body extent -3.01,-4.95 3.01,4.95, height 1.75
DDPAK [mil] "D2-PAK, 3-Pads, Body 9.7x10.4mm (max), TO-263AB, using Vishay Silionix recommended pad sizes"
  rrect8% 135x49.49 smd: 1(-246.06,100) 3(-246.06,-100)
  rrect1% 355x420 smd paste-181.1: 4(155.51,0)
  silkscreen extent -295,-220 344,220, body extent -295,-202 324,202, height 180
DIP-4 [mm] "DIP, 4-Leads, Body 6.86x4.83mm, Pitch 2.54mm"
  rect 1.15x1.15 hole 0.65: 1(-3.81,1.27)
  round 1.15 hole 0.65: 2(-3.81,-1.27) 3(3.81,-1.27) 4(3.81,1.27)
  silkscreen extent -4,-2.41 3.43,2.52, body extent -4.02,-2.41 4.02,2.41, height 5.59
DO-201AD [mm] "Vishay dimensions"
  rect 2.1x2.1 hole 1.6: 1(-10.16,0)
  round 2.1 hole 1.6: 2(10.16,0)
  silkscreen extent -7.47,-2.7 7.57,2.61, body extent -10.82,-2.74 10.82,2.61, height 5.33
FUSE [mm]
  rrect3% 5.1x5.2 smd: 1(0,0) 2(15,0)
  silkscreen extent 2.54,-1.6 12.4,1.6, body extent 2.49,-1.59 12.49,1.59, height 3.18
GBJ [mm] "Micro Commercial Components"
  rect 2.3x2.3 hole 1.6: 1(-12.5,0)
  round 2.3 hole 1.6: 2(-2.5,0) 3(5,0) 4(12.5,0)
  silkscreen extent -15.3,-1.8 15,3.1, body extent -15.25,-1.75 15.05,3.05, height 24.3
GPA_1800x3000 [mm] "TH, 2-Leads, Dia 18mm, Lead Spacing 7.5mm"
  rect 1.55x1.55 hole 1.05: 1(-3.75,0)
  round 1.55 hole 1.05: 2(3.75,0)
  silkscreen extent -9.25,-9.25 9.25,9.25, body extent -9.18,-9.24 9.22,9.24, height 31.5
"inrush res" [mm]
  rect 1.554x1.554 / inner round 1.554 / far side rect 1.554x1.554 hole 1.054: 1(-0.048,-0.033)
  round 1.554 hole 1.054: 2(5.7,-0.033)
  silkscreen extent -3.05,-3.03 2.95,2.97, body extent -3.05,-3.03 2.95,2.96, height 29
LLC_LR [mm]
  round 2 hole 1.2: 1(10.15,-10.1) 1(10.15,-6.3) 2(10.15,6.3) 2(10.15,10.1)
  silkscreen extent -12,-12 12,12
LLC_T [mm]
  round 2.5 hole 1.6: 1(-15.24,-3.745) 3(-15.24,-13.905) 5(-15.24,8.825) 6(-15.24,13.905) 7(15.24,13.905) 9(15.24,3.745) 10(15.24,-3.745) 12(15.24,-13.905)
  silkscreen extent -18.5,-17.5 18.5,17.5
PA2607NL_7R5mm [mm] "SMD, 2-Leads, Body 10.31x7.5mm"
  rect 3.3x3.05 smd: 1(-3.935,0) 2(3.935,0)
  silkscreen extent -5.2,-3.95 5.2,3.95, body extent -5.44,-3.95 5.44,3.95, height 7.5
PFC_L [mm]
  round 2.6 hole 1.6: 1(-17.5,5) 1(-17.5,10) 1(-17.5,15) 2(17.5,-15) 2(17.5,-10) 2(17.5,-5)
  silkscreen extent -20.3,-18 20.3,18
"resonant cap" [mm]
  round 1.6 hole 1: 1(-7.5,0) 2(7.5,0)
  silkscreen extent -9,-4.25 9,4.25
SMA [mm] "Molded Diode, 2-Leads, Body 4.3x2.6mm, IPC Medium Density, based on OnSemi component dimensions and land pattern"
  rect 2x2 smd: 1(-2,0) 2(2,0)
  silkscreen extent -3.66,-1.57 2.79,1.57, body extent -2.6,-1.3 2.6,1.3, height 2.42
SMB [mm] "Molded Diode, 2-Leads, Body 5.4x3.6mm, IPC Medium Density, based on OnSemi component dimensions"
  rect 2.159x2.743 smd: 1(-2.21,0) 2(2.21,0)
  silkscreen extent -3.94,-2.08 3.17,2.08, body extent -2.7,-1.8 2.7,1.8, height 2.32
SMC [mil] "Molded Diode, 2-Leads, Body 6.9x5.8mm, IPC Medium Density, based on OnSemi component dimensions and land patterns"
  rect 110x150 smd: 1(-140.49,0) 2(140.49,0)
  silkscreen extent -221,-123 189,124, body extent -156,-116 156,116, height 91
SOD-123 [mm] "On Semi recommended land pattern"
  rect 0.915x1.22 smd: 1(-1.637,0) 2(1.637,0)
  silkscreen extent -2.74,-1.17 2.03,1.17, body extent -1.93,-0.9 1.93,0.9, height 1.35
sod-323 [mm] "NXP recommended land pattern"
  rect 0.6x0.6 smd paste-0.05: 1(-1.1,0) 2(1.1,0)
  silkscreen extent -2.06,-0.86 1.53,0.86, body extent -1.3,-0.67 1.3,0.68, height 1.1
SOT-23 [mm] "SOT23, 3-Leads, Body 2.9x1.3mm, Pitch 0.95mm, Lead Span 2.5mm, IPC Medium Density"
  rrect50% 1x0.6 smd: 1(-1.2,0.95) 2(-1.2,-0.95) 3(1.2,0)
  silkscreen extent -1.62,-1.5 0.7,1.5, body extent -1.16,-1.45 1.21,1.45, height 1
SOT-363 [mm]
  rect 0.6x0.42 smd mask+0.051: 1(-0.95,0.65) 2(-0.95,0) 3(-0.95,-0.65) 4(0.95,-0.65) 5(0.95,0) 6(0.95,0.65)
  silkscreen extent -0.38,-1.02 0.38,1.02, body extent -1.1,-1.1 1.1,1.1, height 1.12
TE_350429-1 [mm] "Header(Shrouded), 6.35mm, 3x1, TH"
  rect 2.3x2.3 hole 1.78: 1(-6.35,0)
  round 2.3 hole 1.78: 2(0,0) 3(6.35,0)
  silkscreen extent -10.16,-5.08 10.16,4.5, body extent -12.7,-5.08 12.7,3.81, height 14.83
TO-220 [mm]
  rrect25% 1.93x3 hole 1.27: 1(2.54,0)
  oval 1.93x3 hole 1.27: 2(0,2.3) 3(-2.54,0)
  silkscreen extent -5.61,-3.2 5.61,1.49, body extent -5.61,-3.2 5.61,1.49, height 19.42
TO-220-3 [mm] "TH, 3-Leads, Body 10.2235x4.3815mm, Pitch 2.54mm"
  rrect50% 1.6x1.6 hole 1.1: 1(-2.54,0)
  round 1.6 hole 1.1: 2(0,0) 3(2.54,0)
  silkscreen extent -5.3,-1.7 5.3,2.9, body extent -5.27,-1.7 5.28,2.9, height 22.15
TO-220AC [mm]
  rrect50% 1.9x1.9 hole 1.4: 1(-2.54,0)
  round 1.9 hole 1.4: 3(2.54,0)
  silkscreen extent -5.25,-1.64 5.26,3.01, body extent -5.25,-1.64 5.26,3.01, height 19.09
TO-247 [mil] "Standard TO-247"
  rrect50% 95x95 hole 62: 1(-215,0)
  round 95 / inner round 74.8 / far side round 96 hole 62: 2(0,0) 3(215,0)
  silkscreen extent -318,-124 318,81, body extent -318,-124 318,81, height 1007
VAR_S10K275E2 [mm] "EPCOS"
  round 1.6 hole 1.1: 1(-3.75,1.1) 2(3.75,-1.1)
  silkscreen extent -6,-2.7 6,2.7, body extent -5.98,-2.7 5.98,2.7, height 14.99
WCAP-AIG8_3500x3700 [mm] "TH, 2-Leads, Dia 35mm, Pin Spacing 10mm"
  rect 2.5x2.5 hole 2: 1(-5,0)
  round 2.5 hole 2: 2(5,0)
  silkscreen extent -18,-18 18,18, body extent -18,-18 18.01,18, height 39.01
WCAP-FTX2_1500x1000x1600 [mm] "TH, 2-Leads, Body 15x10mm, Pin Spacing 12.5mm"
  round 1.4 hole 0.9: 1(-6.25,0) 2(6.25,0)
  silkscreen extent -7.52,-5 7.48,5, body extent -7.5,-5 7.5,5, height 16
WE-CMB_M [mil] "Wurth"
  rect 70x70 hole 40: 1(-210.63,147.64)
  round 70 hole 40: 2(-210.63,-147.64) 3(210.63,-147.64) 4(210.63,147.64)
  silkscreen extent -335,-435 335,435, body extent -335,-394 335,394, height 1044
WE-CMB_XL [mm] "Wurth"
  rect 2x2 hole 1.3: 1(-12.5,7.5)
  round 2 hole 1.3: 6(12.5,7.5) 7(12.5,-7.5) 12(-12.5,-7.5)
  silkscreen extent -15,-10.18 15,9.3, body extent -15.25,-10.5 15.25,10.5, height 35
WSL2512_-0005 [mm]
  rect 3.05x3.68 smd: 1(-2.16,0) 2(2.16,0)
  silkscreen extent -0.3,-1.8 0.3,1.8, body extent -3.3,-1.71 3.3,1.71, height 0.89

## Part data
C1: library part CMP-0009988-2, "CAP, AL, 330 uF, 450 V, +/- 20%, TH,  861011486022", Cap_Case=35x37mm, Manufacturer="Wurth Elektronik", PartNumber=861011486022, Supplier Part Number 1=732-6640-ND, Tolerance_%=20%, Value1=Unknown, Value2=450V, ValueDisplayed=330uF
C2 C3 C11 C12 C41: "CAP, CERM, 2200 pF, X1 440 VAC/Y2 300 VAC, +/- 20%, Y5U, AEC-Q200 Grade 1, D9.5xT5mm", Cap_Case=9.5x5mm, Manufacturer=Vishay-Bccomponents, Supplier Part Number 1=BC2914-ND, TempCo=Y5U, Tolerance_%=20, ValueDisplayed=2200pF
C4 C10: library part CMP-0012313-3, "CAP, Film, 0.47 uF, 275 V, +/- 10%, TH", Cap_Case=15x10x16mm, Manufacturer="Wurth Elektronik", Supplier Part Number 1=732-5890-ND, Tolerance_%=10%, Value1=Unknown, Value2=275V, ValueDisplayed=0.47uF
C5: library part CMP-0012330-3, "CAP, Film, 0.47 uF, 450 V, +/- 5%, AEC-Q200 Grade 1, TH", Cap_Case=18x8.5x14.5mm, Manufacturer=TDK, Supplier Part Number 1=495-1253-ND, Tolerance_%=5%, Value1=Unknown, Value2=450V, ValueDisplayed=0.47uF
C6 C7: "CAP, CERM, 0.1 µF, 630 V,+/- 20%, X7T, 1210", Cap_Case=1210, Manufacturer=TDK, Supplier Part Number 1=445-14941-1-ND, TempCo=X7T, Tolerance_%=20, Value2=630V, ValueDisplayed=0.1µF
C8 C40: library part CMP-0007006-5, "CAP, CERM, 1 uF, 25 V, +/- 10%, X5R, 0603", Cap_Case=0603, Manufacturer=TDK, Supplier Part Number 1=445-5146-1-ND, TempCo=X5R, Tolerance_%=10%, Value1=Unknown, Value2=25V, ValueDisplayed=1uF
C9 C30: "CAP, CERM, 0.1 µF, 25 V,+/- 10%, X5R, 0603", Cap_Case=0603, Manufacturer=MuRata, Supplier Part Number 1=GRM188R61E104KA01D-ND, TempCo=X5R, Tolerance_%=10, Value2=25V, ValueDisplayed=0.1µF
C13: "CAP, CERM, 100 pF, 630 V,+/- 5%, C0G/NP0, 1206", Cap_Case=1206, Manufacturer=MuRata, Supplier Part Number 1=490-5273-1-ND, TempCo=C0G/NP0, Tolerance_%=5, Value2=630V, ValueDisplayed=100pF
C14: "CAP, CERM, 2.2 µF, 35 V,+/- 10%, X5R, 0603", Cap_Case=0603, Manufacturer=MuRata, Supplier Part Number 1=490-7204-6-ND, TempCo=X5R, Tolerance_%=10, Value2=35V, ValueDisplayed=2.2µF
C15: "CAP, CERM, 0.47 µF, 25 V,+/- 10%, X7R, AEC-Q200 Grade 1, 0603", Cap_Case=0603, Manufacturer=MuRata, Supplier Part Number 1=490-4776-1-ND, TempCo=X7R, Tolerance_%=10, Value2=25V, ValueDisplayed=0.47µF
C16: "CAP, CERM, 1500 pF, 25 V,+/- 10%, X7R, 0603", Cap_Case=0603, Manufacturer=MuRata, Supplier Part Number 1=81-GRM18R71E152KA01D, TempCo=X7R, Tolerance_%=10, Value2=25V, ValueDisplayed=1500pF
C17 C24: "CAP, CERM, 4.7 µF, 25 V,+/- 10%, X5R, 0603", Cap_Case=0603, Manufacturer=MuRata, Supplier Part Number 1=490-7203-1-ND, TempCo=X5R, Tolerance_%=10, Value2=25V, ValueDisplayed=4.7µF
C18: "CAP, CERM, 4700 pF, 16 V,+/- 10%, X7R, 0603", Cap_Case=0603, Manufacturer=MuRata, Supplier Part Number 1=GRM188R71C472KA01D-ND, TempCo=X7R, Tolerance_%=10, Value2=16V, ValueDisplayed=4700pF
C19: "CAP, CERM, 820 pF, 25 V,+/- 5%, C0G/NP0, 0603", Cap_Case=0603, Manufacturer=MuRata, Supplier Part Number 1=81-GRM185C1E821JA01D, TempCo=C0G/NP0, Tolerance_%=5, Value2=25V, ValueDisplayed=820pF
C20: "CAP, CERM, 0.47 µF, 16 V,+/- 10%, X7R, 0603", Cap_Case=0603, Manufacturer=MuRata, Supplier Part Number 1=490-3295-1-ND, TempCo=X7R, Tolerance_%=10, Value2=16V, ValueDisplayed=0.47µF
C21: "CAP, CERM, 2.2 µF, 16 V,+/- 10%, X7R, 0603", Cap_Case=0603, Manufacturer=MuRata, Supplier Part Number 1=81-GRM188Z71C225KE3D, TempCo=X7R, Tolerance_%=10, Value2=16V, ValueDisplayed=2.2µF
C22 C53: library part CMP-0007044-5, "CAP, CERM, 0.1 uF, 50 V, +/- 10%, X7R, 0603", Cap_Case=0603, Manufacturer=TDK, Supplier Part Number 1=445-1314-1-ND, TempCo=X7R, Tolerance_%=10%, Value1="0.0296 ohm", Value2=50V, ValueDisplayed=0.1uF
C23: library part CMP-0007121-4, "CAP, CERM, 2.2 uF, 16 V, +/- 10%, X7R, 0603", Cap_Case=0603, Manufacturer="Taiyo Yuden", Supplier Part Number 1=EMK107BB7225KA-T-ND, TempCo=X7R, Tolerance_%=10%, Value1=Unknown, Value2=16V, ValueDisplayed=2.2uF
C25: "CAP, CERM, 68 pF, 1000 V,+/- 5%, U2J, 1206", Cap_Case=1206, Manufacturer=MuRata, Supplier Part Number 1=490-4300-1-ND, TempCo=U2J, Tolerance_%=5, Value2=1000V, ValueDisplayed=68pF
C26: "CAP, CERM, 330 pF, 630 V,+/- 5%, C0G/NP0, 1206", Cap_Case=1206, Manufacturer=MuRata, Supplier Part Number 1=490-5276-1-ND, TempCo=C0G/NP0, Tolerance_%=5, Value2=630V, ValueDisplayed=330pF
C27 C28 C29: library part CMP-0009861-2, "CAP, AL, 680 uF, 80 V, +/- 20%, 0.041 ohm, AEC-Q200 Grade 1, TH", Cap_Case=18x30mm, Manufacturer=Chemi-Con, Supplier Part Number 1=565-3420-ND, Tolerance_%=20%, Value1="0.041 ohm", Value2=80V, ValueDisplayed=680uF
C31: "CAP, Film, 0.082 µF, 300 VAC/630 VDC,+/- 5%, AEC-Q200 Grade 2, TH", Cap_Case=26.5x10x18.5mm, Manufacturer=Kemet, Supplier Part Number 1=399-7662-ND, Tolerance_%=5, Value2=630V, ValueDisplayed=0.082µF
C32 C33 C34 C35: "CAP, CERM, 10 µF, 63 V,+/- 10%, X7R, 1210", Cap_Case=1210, Manufacturer=MuRata, Supplier Part Number 1=490-9970-1-ND, TempCo=X7R, Tolerance_%=10, Value2=63V, ValueDisplayed=10µF
C38 C49 C56: "CAP, CERM, 100 pF, 25 V,+/- 10%, X7R, 0603", Cap_Case=0603, Manufacturer=AVX, Supplier Part Number 1=55J3899, TempCo=X7R, Tolerance_%=10, Value2=25V, ValueDisplayed=100pF
C39: "CAP, CERM, 8200 pF, 25 V,+/- 10%, X7R, 0603", Cap_Case=0603, Manufacturer=MuRata, Supplier Part Number 1=GRM188R71E822KA01D-ND, TempCo=X7R, Tolerance_%=10, Value2=25V, ValueDisplayed=8200pF
C42: library part CMP-0007434-4, "CAP, CERM, 0.1 uF, 50 V, +/- 10%, X7R, 0603", Cap_Case=0603, Manufacturer=MuRata, Supplier Part Number 1=490-1519-1-ND, TempCo=X7R, Tolerance_%=10%, Value1=Unknown, Value2=50V, ValueDisplayed=0.1uF
C43: library part CMP-0007137-5, "CAP, CERM, 1 uF, 16 V, +/- 20%, X7R, AEC-Q200 Grade 1, 0603", Cap_Case=0603, Manufacturer=MuRata, TempCo=X7R, Tolerance_%=20%, Value1=Unknown, Value2=16V, ValueDisplayed=1uF
C44 C45: library part CMP-0007433-4, "CAP, CERM, 0.01 uF, 50 V, +/- 10%, X7R, 0603", Cap_Case=0603, Manufacturer=MuRata, Supplier Part Number 1=490-1512-1-ND, TempCo=X7R, Tolerance_%=10%, Value1=Unknown, Value2=50V, ValueDisplayed=0.01uF
C46: "CAP, CERM, 0.01 µF, 25 V,+/- 10%, X7R, 0603", Cap_Case=0603, Manufacturer=MuRata, Supplier Part Number 1=490-1520-1-ND, TempCo=X7R, Tolerance_%=10, Value2=25V, ValueDisplayed=0.01µF
C47: "CAP, CERM, 1 µF, 25 V,+/- 10%, X7R, 1206", Cap_Case=1206, Manufacturer=AVX, Supplier Part Number 1=478-1567-1-ND, TempCo=X7R, Tolerance_%=10, Value1="0.013 ohm", Value2=25V, ValueDisplayed=1µF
